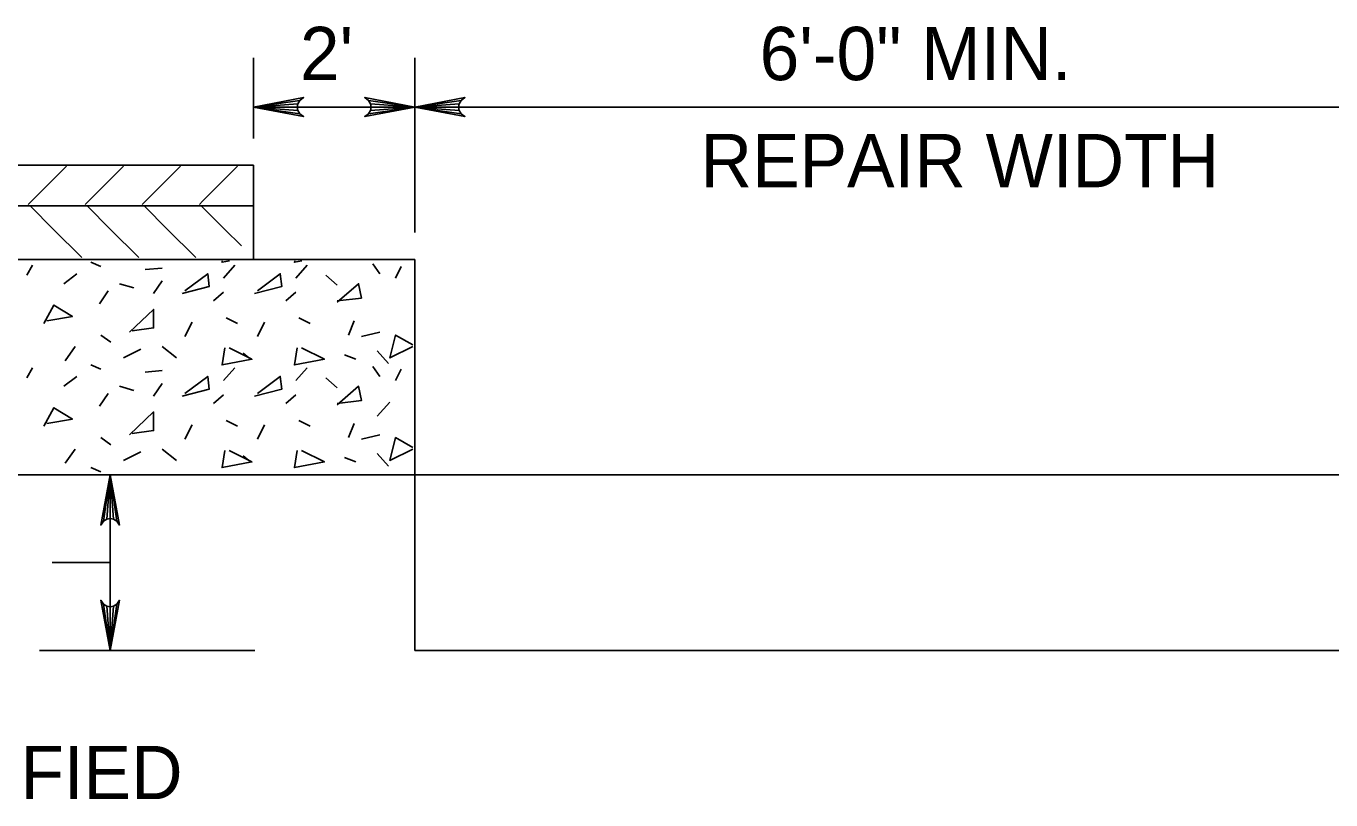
# Model space of a CAD drawing. Extents: x 3.47 to 10.73, y 1.11 to 10.92.
# Drawn here: x 5.858 to 7.328, y 10.046 to 10.918 of the extents above; entities that cross this region are included whole.
import ezdxf

# ---------------------------------------------------------------- set-up
doc = ezdxf.new("R2010")
doc.units = 0
for name, color, linetype in [('DETL-DIMS', 7, 'Continuous'), ('DETL-LINE', 7, 'Continuous'), ('DETL-NOTE', 7, 'Continuous'), ('DETL-PATT', 7, 'Continuous')]:
    doc.layers.add(name, color=color, linetype=linetype)

msp = doc.modelspace()

# ---------------------------------------------------------------- linework, layer by layer
at = {"layer": 'DETL-DIMS'}
for p, q in [((6.114, 10.7911), (6.114, 10.882)), ((6.2958, 10.685), (6.2958, 10.882)), ((6.2958, 10.8264), (6.114, 10.8264)), ((6.2958, 10.8264), (7.6291, 10.8264)), ((5.9526, 10.2145), (5.9526, 10.4123)), ((5.8874, 10.3134), (5.9526, 10.3134)), ((5.873, 10.2145), (6.1155, 10.2145))]:
    msp.add_line(p, q, dxfattribs=at)
for points in [[(6.114, 10.8264), (6.1705, 10.837), (6.1661, 10.8339), (6.1639, 10.8302), (6.1632, 10.8264), (6.1639, 10.8226), (6.1661, 10.8188), (6.1705, 10.8158), (6.114, 10.8264), (6.1661, 10.8188), (6.1639, 10.8226), (6.114, 10.8264), (6.1632, 10.8264), (6.1639, 10.8302), (6.114, 10.8264), (6.1661, 10.8339)], [(6.2958, 10.8264), (6.2393, 10.8158), (6.2437, 10.8188), (6.2459, 10.8226), (6.2466, 10.8264), (6.2459, 10.8302), (6.2437, 10.8339), (6.2393, 10.837), (6.2958, 10.8264), (6.2437, 10.8339), (6.2459, 10.8302), (6.2958, 10.8264), (6.2466, 10.8264), (6.2459, 10.8226), (6.2958, 10.8264), (6.2437, 10.8188)], [(6.2958, 10.8264), (6.3523, 10.8158), (6.3479, 10.8188), (6.3457, 10.8226), (6.345, 10.8264), (6.3457, 10.8302), (6.3479, 10.8339), (6.3523, 10.837), (6.2958, 10.8264), (6.3479, 10.8339), (6.3457, 10.8302), (6.2958, 10.8264), (6.345, 10.8264), (6.3457, 10.8226), (6.2958, 10.8264), (6.3479, 10.8188)], [(5.9526, 10.4123), (5.9632, 10.3558), (5.9602, 10.3601), (5.9564, 10.3624), (5.9526, 10.363), (5.9489, 10.3624), (5.9451, 10.3601), (5.9421, 10.3558), (5.9526, 10.4123), (5.9451, 10.3601), (5.9489, 10.3624), (5.9526, 10.4123), (5.9526, 10.363), (5.9564, 10.3624), (5.9526, 10.4123), (5.9602, 10.3601)], [(5.9526, 10.2145), (5.9421, 10.271), (5.9451, 10.2667), (5.9489, 10.2644), (5.9526, 10.2638), (5.9564, 10.2644), (5.9602, 10.2667), (5.9632, 10.271), (5.9526, 10.2145), (5.9602, 10.2667), (5.9564, 10.2644), (5.9526, 10.2145), (5.9526, 10.2638), (5.9489, 10.2644), (5.9526, 10.2145), (5.9451, 10.2667)]]:
    msp.add_lwpolyline(points, dxfattribs=at)
at = {"layer": 'DETL-LINE'}
for p, q in [((5.5382, 10.7608), (6.114, 10.7608)), ((6.114, 10.6547), (6.114, 10.7608)), ((5.5382, 10.7153), (6.114, 10.7153)), ((5.5382, 10.6547), (6.2958, 10.6547)), ((6.2958, 10.2145), (6.2958, 10.6547)), ((5.5382, 10.4123), (6.2958, 10.4123)), ((6.2958, 10.4123), (7.6291, 10.4123)), ((6.2958, 10.2145), (7.6291, 10.2145))]:
    msp.add_line(p, q, dxfattribs=at)
at = {"layer": 'DETL-PATT'}
for p, q in [((5.8639, 10.7203), (5.9034, 10.7598)), ((5.9282, 10.7203), (5.9677, 10.7598)), ((5.9925, 10.7203), (6.0319, 10.7598)), ((6.0567, 10.7203), (6.0962, 10.7598)), ((5.8602, 10.7167), (5.8639, 10.7203)), ((5.8885, 10.6891), (5.8627, 10.7148)), ((5.9245, 10.7167), (5.9282, 10.7203)), ((5.9527, 10.6891), (5.927, 10.7148)), ((5.9888, 10.7167), (5.9925, 10.7203)), ((6.017, 10.6891), (5.9913, 10.7148)), ((6.0531, 10.7167), (6.0567, 10.7203)), ((6.0813, 10.6891), (6.0556, 10.7148)), ((5.9206, 10.657), (5.8885, 10.6891)), ((5.9849, 10.657), (5.9527, 10.6891)), ((6.0492, 10.657), (6.017, 10.6891)), ((6.1005, 10.67), (6.0813, 10.6891)), ((5.8587, 10.6371), (5.8651, 10.6483)), ((5.9309, 10.6516), (5.9422, 10.6467)), ((5.9919, 10.6435), (6.0112, 10.6451)), ((6.0802, 10.6339), (6.093, 10.6483)), ((6.1618, 10.6339), (6.1746, 10.6483)), ((6.2485, 10.6499), (6.2565, 10.6387)), ((6.2805, 10.6467), (6.2741, 10.6339)), ((5.9149, 10.6387), (5.9004, 10.6275)), ((5.963, 10.6275), (5.9791, 10.6227)), ((6.0015, 10.6163), (6.0112, 10.6307)), ((6.1955, 10.6371), (6.2083, 10.6259)), ((5.9502, 10.6195), (5.9406, 10.605)), ((6.0689, 10.6082), (6.0802, 10.6179)), ((6.1506, 10.6082), (6.1618, 10.6179)), ((6.0368, 10.5681), (6.0449, 10.5842)), ((6.0834, 10.589), (6.0962, 10.5826)), ((6.1185, 10.5681), (6.1265, 10.5842)), ((6.165, 10.589), (6.1779, 10.5826)), ((6.2276, 10.5858), (6.2212, 10.5697)), ((5.9422, 10.5697), (5.9534, 10.5617)), ((6.2565, 10.5729), (6.2356, 10.5681)), ((5.9133, 10.5569), (5.902, 10.5408)), ((5.9871, 10.5537), (5.9678, 10.544)), ((6.0112, 10.5569), (6.0272, 10.544)), ((6.1023, 10.5493), (6.1089, 10.544)), ((6.2164, 10.5473), (6.2292, 10.5424)), ((6.2533, 10.5521), (6.2661, 10.5376)), ((5.8587, 10.5216), (5.8651, 10.5328)), ((5.9309, 10.536), (5.9422, 10.5312)), ((5.9919, 10.528), (6.0112, 10.5296)), ((6.0802, 10.5184), (6.093, 10.5328)), ((6.1618, 10.5184), (6.1746, 10.5328)), ((6.2485, 10.5344), (6.2565, 10.5232)), ((6.2805, 10.5312), (6.2741, 10.5184)), ((5.9149, 10.5232), (5.9004, 10.512)), ((5.963, 10.512), (5.9791, 10.5071)), ((6.0015, 10.5007), (6.0112, 10.5152)), ((6.1955, 10.5216), (6.2083, 10.5103)), ((5.9502, 10.5039), (5.9406, 10.4895)), ((6.0689, 10.4927), (6.0802, 10.5023)), ((6.1506, 10.4927), (6.1618, 10.5023)), ((6.2677, 10.4943), (6.2533, 10.4783)), ((6.0368, 10.4526), (6.0449, 10.4686)), ((6.0834, 10.4734), (6.0962, 10.467)), ((6.1185, 10.4526), (6.1265, 10.4686)), ((6.165, 10.4734), (6.1779, 10.467)), ((6.2276, 10.4702), (6.2212, 10.4542)), ((5.9422, 10.4542), (5.9534, 10.4462)), ((6.2565, 10.4574), (6.2356, 10.4526)), ((5.9133, 10.4413), (5.902, 10.4253)), ((5.9871, 10.4381), (5.9678, 10.4285)), ((6.0112, 10.4413), (6.0272, 10.4285)), ((6.2533, 10.4365), (6.2661, 10.4221)), ((5.9309, 10.4205), (5.9422, 10.4157)), ((6.1023, 10.4337), (6.1089, 10.4285)), ((6.2164, 10.4317), (6.2292, 10.4269))]:
    msp.add_line(p, q, dxfattribs=at)
for points in [[(6.0788, 10.6531), (6.0786, 10.6516), (6.0869, 10.6531)], [(6.1605, 10.6531), (6.1602, 10.6516), (6.1686, 10.6531)], [(6.0336, 10.6163), (6.0641, 10.6243), (6.0625, 10.6387), (6.0368, 10.6195)], [(6.1153, 10.6163), (6.1458, 10.6243), (6.1442, 10.6387), (6.1185, 10.6195)], [(6.2083, 10.6082), (6.2356, 10.6114), (6.2324, 10.6275), (6.2083, 10.6066)], [(5.878, 10.5826), (5.8892, 10.6034), (5.9101, 10.5906), (5.8812, 10.5858)], [(5.9775, 10.5745), (6.0015, 10.5777), (6.0015, 10.5986), (5.9743, 10.5729)], [(6.2934, 10.5569), (6.2677, 10.544), (6.2741, 10.5697), (6.2934, 10.5585)], [(6.0818, 10.5553), (6.0786, 10.536), (6.1122, 10.5424), (6.0866, 10.5553)], [(6.1634, 10.5553), (6.1602, 10.536), (6.1939, 10.5424), (6.1682, 10.5553)], [(6.0336, 10.5007), (6.0641, 10.5087), (6.0625, 10.5232), (6.0368, 10.5039)], [(6.1153, 10.5007), (6.1458, 10.5087), (6.1442, 10.5232), (6.1185, 10.5039)], [(6.2083, 10.4927), (6.2356, 10.4959), (6.2324, 10.512), (6.2083, 10.4911)], [(5.878, 10.467), (5.8892, 10.4879), (5.9101, 10.475), (5.8812, 10.4702)], [(5.9775, 10.459), (6.0015, 10.4622), (6.0015, 10.4831), (5.9743, 10.4574)], [(6.2934, 10.4413), (6.2677, 10.4285), (6.2741, 10.4542), (6.2934, 10.443)], [(6.0818, 10.4397), (6.0786, 10.4205), (6.1122, 10.4269), (6.0866, 10.4397)], [(6.1634, 10.4397), (6.1602, 10.4205), (6.1939, 10.4269), (6.1682, 10.4397)]]:
    msp.add_lwpolyline(points, dxfattribs=at)

# ---------------------------------------------------------------- texts
at = {"layer": 'DETL-NOTE'}
for s, p in [("2'", (6.1664, 10.8567)), ('6\'-0" MIN.', (6.6842, 10.8567)), ('REPAIR WIDTH', (6.6177, 10.7361)), ('OR AS SPECIFIED', (5.3387, 10.0471))]:
    msp.add_text(s, height=0.06, dxfattribs=at).set_placement(p)

doc.saveas('drawing.dxf')
